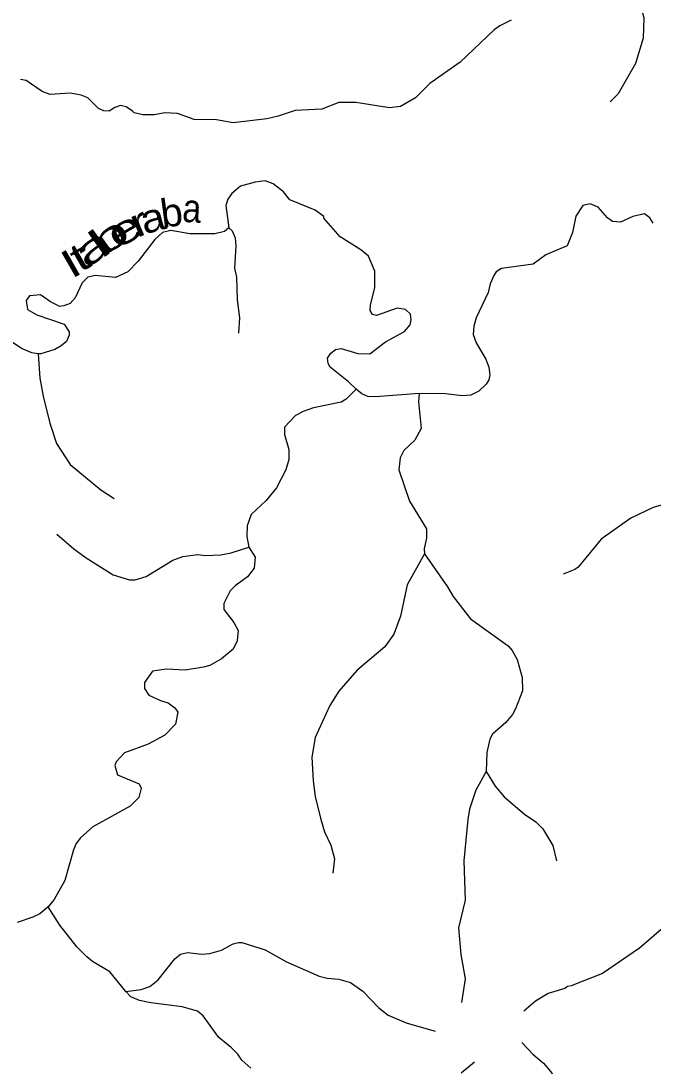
# Model space of a CAD drawing. Extents: x 346.5 to 372.4, y 7400.3 to 7428.2.
# Drawn here: x 362.273 to 364.068, y 7416.929 to 7419.897 of the extents above; entities that cross this region are included whole.
import ezdxf
from ezdxf.enums import TextEntityAlignment as Align

# ---------------------------------------------------------------- set-up
doc = ezdxf.new("R2010")
doc.units = 0
doc.header["$LTSCALE"] = 0.032
doc.layers.add('61', color=7, linetype='Continuous')
doc.layers.add('7', color=7, linetype='Continuous', lineweight=25)

msp = doc.modelspace()

# ---------------------------------------------------------------- linework, layer by layer
at = {"layer": '7'}
for points in [[(363.9092, 7420.1146), (363.9264, 7420.076), (363.9534, 7420.0441), (363.9718, 7420.029), (364.022, 7419.9628), (364.0347, 7419.9342), (364.0419, 7419.9055), (364.0403, 7419.8481), (364.018, 7419.7764), (363.9694, 7419.6903), (363.9463, 7419.6672)], [(363.665, 7419.8991), (363.6331, 7419.8831), (363.6172, 7419.872), (363.5207, 7419.7795), (363.4339, 7419.7198), (363.3932, 7419.6783), (363.351, 7419.6544), (363.3191, 7419.6504), (363.2235, 7419.6656), (363.1756, 7419.6656), (363.1278, 7419.6464), (363.0513, 7419.6425), (363.0035, 7419.6265), (362.9716, 7419.6193), (362.876, 7419.6074), (362.8282, 7419.6162), (362.7644, 7419.617), (362.7174, 7419.6337), (362.6815, 7419.6361), (362.6513, 7419.6305), (362.6194, 7419.6305), (362.5947, 7419.6361), (362.5899, 7419.6409), (362.5716, 7419.6528), (362.5556, 7419.6568), (362.5397, 7419.6512), (362.5237, 7419.6409), (362.5078, 7419.6417), (362.4935, 7419.648), (362.4632, 7419.6791), (362.4441, 7419.6863), (362.4122, 7419.6919), (362.3556, 7419.6879), (362.3333, 7419.6966), (362.2878, 7419.7277), (362.2719, 7419.7309)], [(363.2244, 7418.8509), (363.2035, 7418.8718), (363.1509, 7418.9133), (363.1453, 7418.9244), (363.1438, 7418.9396), (363.1525, 7418.9531), (363.1661, 7418.9635), (363.182, 7418.9666), (363.2298, 7418.9523), (363.2633, 7418.9515), (363.3079, 7418.9858), (363.3621, 7419.0153), (363.3781, 7419.0344), (363.3812, 7419.048), (363.3789, 7419.0647), (363.3653, 7419.0774), (363.3414, 7419.0814), (363.2824, 7419.0607), (363.2713, 7419.0631), (363.2649, 7419.075), (363.2657, 7419.091), (363.2776, 7419.1388), (363.2776, 7419.1866), (363.2601, 7419.2289), (363.2378, 7419.2472), (363.1796, 7419.2838), (363.1334, 7419.3372), (363.1326, 7419.342), (363.1087, 7419.3595), (363.0362, 7419.389), (363.0186, 7419.4113), (362.9892, 7419.4344), (362.966, 7419.4432), (362.9382, 7419.4392), (362.8967, 7419.4273), (362.872, 7419.4074), (362.86, 7419.3906), (362.8545, 7419.3731), (362.8633, 7419.3091)], [(364.0682, 7419.3229), (364.0587, 7419.338), (364.0435, 7419.3492), (364.0108, 7419.3412), (363.9758, 7419.3253), (363.9527, 7419.3277), (363.9383, 7419.338), (363.912, 7419.3683), (363.8897, 7419.3779), (363.8682, 7419.3731), (363.849, 7419.3428), (363.8395, 7419.2966), (363.8244, 7419.2583), (363.7638, 7419.2328), (363.7271, 7419.2065), (363.6379, 7419.1938), (363.6227, 7419.1842), (363.6155, 7419.1739), (363.6052, 7419.15), (363.5996, 7419.1261), (363.5661, 7419.0543), (363.559, 7419.0304), (363.5574, 7419.0065), (363.5661, 7418.9826), (363.5932, 7418.9364), (363.602, 7418.9141), (363.6044, 7418.8918), (363.6012, 7418.8782), (363.594, 7418.8654), (363.5733, 7418.8455), (363.5502, 7418.8343), (363.5263, 7418.8328), (363.4785, 7418.8383), (363.4036, 7418.839)], [(362.8633, 7419.3091), (362.8513, 7419.299), (362.8234, 7419.2926), (362.7523, 7419.2921), (362.6986, 7419.3018), (362.6752, 7419.2963), (362.6528, 7419.2759), (362.6058, 7419.2145), (362.5763, 7419.1842), (362.5413, 7419.1683), (362.4839, 7419.1738), (362.4624, 7419.1691), (362.4464, 7419.1531), (362.4265, 7419.1109), (362.4122, 7419.0949), (362.3946, 7419.0878), (362.3827, 7419.0862), (362.3755, 7419.0894), (362.3564, 7419.0989), (362.3285, 7419.1189), (362.2974, 7419.1165), (362.2878, 7419.1029), (362.2918, 7419.0774), (362.3181, 7419.0623), (362.3954, 7419.036), (362.4098, 7419.0137), (362.4098, 7419.0049), (362.4026, 7418.9866), (362.3867, 7418.9746), (362.3691, 7418.9642), (362.3296, 7418.9519), (362.3214, 7418.9519)], [(362.8633, 7419.3091), (362.8725, 7419.3006), (362.8808, 7419.2814), (362.8832, 7419.2583), (362.8792, 7419.1946), (362.8847, 7419.1691), (362.8871, 7419.1053), (362.8935, 7419.0543), (362.8903, 7419.0105)], [(362.3214, 7418.9519), (362.3035, 7418.9547), (362.2743, 7418.9667), (362.2512, 7418.9826), (362.2217, 7419.0145), (362.2066, 7419.0256), (362.189, 7419.0336), (362.1527, 7419.0393)], [(362.3214, 7418.9519), (362.3269, 7418.8822), (362.3364, 7418.8312), (362.3548, 7418.7547), (362.3739, 7418.6973), (362.413, 7418.6375), (362.4998, 7418.565), (362.5373, 7418.5403)], [(363.2244, 7418.8509), (363.1964, 7418.8224), (363.182, 7418.8144), (363.1039, 7418.7985), (363.0744, 7418.7881), (363.0521, 7418.7762), (363.021, 7418.7435), (363.0218, 7418.7228), (363.0338, 7418.6798), (363.0338, 7418.6511), (363.025, 7418.6224), (362.9987, 7418.5706), (362.9692, 7418.5355), (362.9262, 7418.4949), (362.915, 7418.463), (362.9142, 7418.4327), (362.9196, 7418.4025)], [(363.4036, 7418.839), (363.2793, 7418.8296), (363.2577, 7418.8304), (363.2409, 7418.8379), (363.2244, 7418.8509)], [(363.4036, 7418.839), (363.402, 7418.8152), (363.4099, 7418.7395), (363.3916, 7418.706), (363.3605, 7418.6774), (363.3494, 7418.6559), (363.3462, 7418.6224), (363.3765, 7418.5331), (363.4243, 7418.4542), (363.4243, 7418.4295), (363.4179, 7418.398), (363.4193, 7418.3835)], [(364.2254, 7418.6602), (364.222, 7418.6455), (364.2188, 7418.6439), (364.2093, 7418.6224), (364.1798, 7418.5745), (364.1639, 7418.5546), (364.124, 7418.5315), (364.0682, 7418.5156), (364.0045, 7418.4853), (363.9208, 7418.4255), (363.8554, 7418.3458), (363.8459, 7418.3387), (363.8124, 7418.3259)], [(362.3747, 7418.4399), (362.4233, 7418.3976), (362.4584, 7418.3721), (362.5349, 7418.3243), (362.5811, 7418.31), (362.5971, 7418.31), (362.6289, 7418.3195), (362.7039, 7418.3657), (362.7325, 7418.3761), (362.7748, 7418.3817), (362.7963, 7418.3785), (362.8409, 7418.3809), (362.8696, 7418.3865), (362.9196, 7418.4025)], [(362.9196, 7418.4025), (362.9381, 7418.3745), (362.935, 7418.3427), (362.9158, 7418.3187), (362.8808, 7418.2924), (362.8672, 7418.2781), (362.8489, 7418.243), (362.8489, 7418.2255), (362.8776, 7418.1888), (362.8895, 7418.1657), (362.8871, 7418.137), (362.876, 7418.1131), (362.8425, 7418.0852), (362.8091, 7418.0669), (362.7915, 7418.0613), (362.7389, 7418.0533), (362.6863, 7418.0565), (362.6465, 7418.0502), (362.6241, 7418.0183), (362.6241, 7418.0008), (362.6361, 7417.9824), (362.6688, 7417.9673), (362.6911, 7417.9601), (362.7102, 7417.9466), (362.7182, 7417.9338), (362.7118, 7417.8995), (362.6815, 7417.8685), (362.6337, 7417.8429), (362.5668, 7417.8182), (362.5429, 7417.7928), (362.5397, 7417.7824), (362.5468, 7417.7561), (362.609, 7417.7306), (362.6138, 7417.7178), (362.6074, 7417.6915), (362.5827, 7417.6668), (362.4767, 7417.6087), (362.4424, 7417.5768), (362.4297, 7417.5609), (362.4217, 7417.5433), (362.3978, 7417.4557), (362.3667, 7417.4023), (362.3501, 7417.3808)], [(363.4193, 7418.3835), (363.3701, 7418.2956), (363.351, 7418.2064), (363.3318, 7418.1554), (363.3063, 7418.1195), (363.2267, 7418.0525), (363.1756, 7417.9936), (363.1501, 7417.9529), (363.1087, 7417.8621), (363.0991, 7417.8063), (363.1023, 7417.7394), (363.1087, 7417.6947), (363.1238, 7417.6326), (363.135, 7417.5943), (363.1525, 7417.5561), (363.1629, 7417.5178), (363.1589, 7417.4772)], [(363.4193, 7418.3835), (363.484, 7418.2901), (363.5, 7418.2622), (363.5494, 7418.1992), (363.6562, 7418.1227), (363.6681, 7418.1092), (363.6825, 7418.0836), (363.696, 7418.0326), (363.6968, 7417.9944), (363.6777, 7417.9434), (363.6689, 7417.9274), (363.6498, 7417.9051), (363.6123, 7417.8717), (363.6044, 7417.8573), (363.5956, 7417.8191), (363.5941, 7417.7652)], [(363.5941, 7417.7652), (363.5645, 7417.7123), (363.547, 7417.6581), (363.5422, 7417.6294), (363.5311, 7417.5114), (363.5343, 7417.3999), (363.5151, 7417.3218), (363.5223, 7417.246), (363.5343, 7417.1767), (363.5239, 7417.109)], [(363.5941, 7417.7652), (363.6195, 7417.7242), (363.645, 7417.6939), (363.7032, 7417.6445), (363.7351, 7417.623), (363.755, 7417.6023), (363.7837, 7417.5553), (363.7941, 7417.5122)], [(362.3501, 7417.3808), (362.3269, 7417.3616), (362.3062, 7417.352), (362.2623, 7417.3369)], [(362.5708, 7417.141), (362.5253, 7417.1966), (362.4759, 7417.2261), (362.46, 7417.2389), (362.4313, 7417.2676), (362.3835, 7417.3289), (362.3501, 7417.3808)], [(364.1113, 7417.3337), (364.03, 7417.2636), (363.924, 7417.1918), (363.8355, 7417.1568), (363.8252, 7417.1552), (363.8172, 7417.1496), (363.7702, 7417.1353), (363.7343, 7417.113), (363.7008, 7417.0851)], [(362.5708, 7417.141), (362.6146, 7417.1464), (362.6385, 7417.1552), (362.6624, 7417.1743), (362.7102, 7417.2333), (362.7262, 7417.2468), (362.7461, 7417.2516), (362.7867, 7417.2468), (362.8091, 7417.2484), (362.8425, 7417.258), (362.876, 7417.2763), (362.8903, 7417.2803), (362.8999, 7417.2795), (362.966, 7417.2588), (363.0274, 7417.2245), (363.1199, 7417.1847), (363.1422, 7417.1783), (363.1756, 7417.1759), (363.2091, 7417.1663), (363.2442, 7417.1416), (363.2896, 7417.0946), (363.3159, 7417.0731), (363.3669, 7417.0516), (363.449, 7417.0285)], [(362.9254, 7416.9233), (362.8999, 7416.9456), (362.8887, 7416.9623), (362.8704, 7416.9807), (362.8353, 7417.0102), (362.7899, 7417.0715), (362.774, 7417.0851), (362.731, 7417.097), (362.6417, 7417.1082), (362.6098, 7417.1153), (362.5853, 7417.1252), (362.5708, 7417.141)], [(363.6953, 7416.9958), (363.7263, 7416.9631), (363.7566, 7416.9368), (363.7781, 7416.9121), (363.8467, 7416.8045), (363.8682, 7416.7822), (363.9327, 7416.7352), (363.9582, 7416.7185), (363.9965, 7416.7009), (364.073, 7416.6794), (364.1113, 7416.6651), (364.2627, 7416.5734), (364.3519, 7416.5463), (364.3886, 7416.5168), (364.4117, 7416.4826), (364.4228, 7416.4746), (364.4404, 7416.4682), (364.4731, 7416.4642), (364.4986, 7416.4666), (364.5241, 7416.4754), (364.5815, 7416.5113), (364.6054, 7416.5216), (364.6691, 7416.5248), (364.6893, 7416.5267)], [(363.5606, 7416.94), (363.5231, 7416.9089)]]:
    msp.add_lwpolyline(points, dxfattribs=at)

# ---------------------------------------------------------------- texts
at = {"layer": '61'}
for s, rotation, width, p in [('b', 7.587, 1.05, (362.7056, 7419.3135)), ('a', 356.548, 0.9, (362.7563, 7419.3251)), ('r', 23.199, 1.35, (362.624, 7419.2895)), ('a', 14.603, 1.15, (362.6563, 7419.2993)), ('e', 30.589, 1.65, (362.5869, 7419.271)), ('b', 35.57, 1.85, (362.5456, 7419.2515)), ('a', 35.57, 1.75, (362.5009, 7419.2218)), ('I', 29.887, 1.4, (362.4339, 7419.1732)), ('t', 29.887, 1.45, (362.4591, 7419.1921))]:
    msp.add_text(s, height=0.08, rotation=rotation, dxfattribs=dict(at, width=width)).set_placement(p, align=Align.CENTER)

doc.saveas('drawing.dxf')
